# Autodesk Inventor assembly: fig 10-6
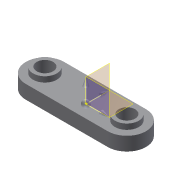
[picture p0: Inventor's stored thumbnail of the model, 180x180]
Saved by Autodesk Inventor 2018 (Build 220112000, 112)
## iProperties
Created: 2010-08
Part Number: fig 10-6
Document SubType Name: Assembly
Designer: CADSoft
Author: CADSoft
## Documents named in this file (2)
- E:\_Deepak\Inventor\Autodesk Inventor_2017_Project\Resources\Inventor_2018_Part\c10_Inv_2018\c10_inv_2018_prt\fig 10-6.iam
- E:\_Deepak\Inventor\Autodesk Inventor_2017_Project\Resources\Inventor_2018_Part\c10_Inv_2018\c10_inv_2018_prt\Part6.ipt
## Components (1 placed, 1 different names)
1. Part6:1
